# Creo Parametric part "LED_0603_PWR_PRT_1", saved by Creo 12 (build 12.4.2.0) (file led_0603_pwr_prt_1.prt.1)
Units: Custom; MM, KILOGRAM, SECS

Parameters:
  PTC_WM_ITERATION = "0"
  PTC_WM_VERSION = "-.0"
  PTC_WM_LIFECYCLE_STATE = "In Work"
  PTC_WM_LIFECYCLE = "MO_CADDocument"
  PTC_WM_CREATED_BY = "Maximilian Roepper (Z0017RMS: MO)"
  PTC_WM_CREATED_ON = "18-Sep-26 11:36:42 AM"
  PTC_WM_MODIFIED_BY = "Maximilian Roepper (Z0017RMS: MO)"
  PTC_WM_MODIFIED_ON = "18-Sep-26 11:36:46 AM"
  PDMLINKNUMBER = "PDM000071454844"
  PTC_WM_NAME = "led_0603_pwr_prt_1.prt"
  PTC_WM_NUMBER = "PDM000071454844"

Other parameters: WEIGHT, WEIGHT_FACTOR, WEIGHT_ADD, _MASS_TEMP, _DIFF_TEMP, MC_ERRORS, SUPPLIER

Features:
  1. coordinate system
  2. datum plane "PRT_YZ"
  3. datum plane "PRT_XY"
  4. datum plane "PRT_XZ"
  5. coordinate system
  6. datum axis
  7. datum axis
  8. datum axis
  9. coordinate system
  10. imported feature
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
Other named items: PRT, SIEMENS_MO, DRW_VIEW_ORG, PRT_X, PRT_Y, PRT_Z, CS0, ROUGH_GROB

Layers: 00_STD_CSYS-KSYS, 01_STD_PLANES-EBENEN, 02_STD_AXES-ACHSEN, 03_STD_CSYS-KSYS, 24_IMPORT_FEAT-IMPORT_KE

Surfaces: 42 plane, 8 cylinder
